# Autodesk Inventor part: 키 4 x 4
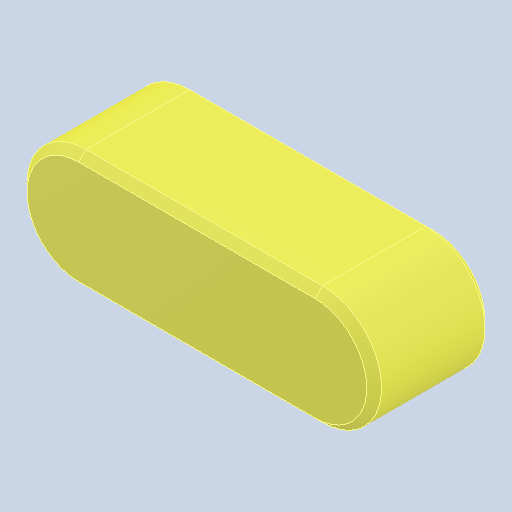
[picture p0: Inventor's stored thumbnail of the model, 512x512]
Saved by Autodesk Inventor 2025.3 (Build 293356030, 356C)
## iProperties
Created: 2025-08
Part Number: 키 4 x 4
Material: 강철, 연강
Description: 키 및 해당 키홈
Document SubType Name: Modeling
Designer: user
Density: 7.86 g/cm^3
Appearance: 기본값
Author: jhkim
Sending System: Autodesk Inventor 2026
Preprocessor: ST-DEVELOPER v20.1
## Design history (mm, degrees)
sketch "스케치1"
  geometry: 1 further point
  constraints: 1 other
feature "Solid1"
node "솔리드1"
